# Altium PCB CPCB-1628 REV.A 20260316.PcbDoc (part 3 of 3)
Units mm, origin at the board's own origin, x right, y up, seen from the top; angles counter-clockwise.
Board outline 103 x 58.8 mm, 4 copper layers (Top Layer 1, Layer1, Layer2, Bottom Layer 1), stack 0.603 mm thick; 176 components, 137 nets, 518 pads, 340 vias.
Unrouted connection lines stored in the file: 10.
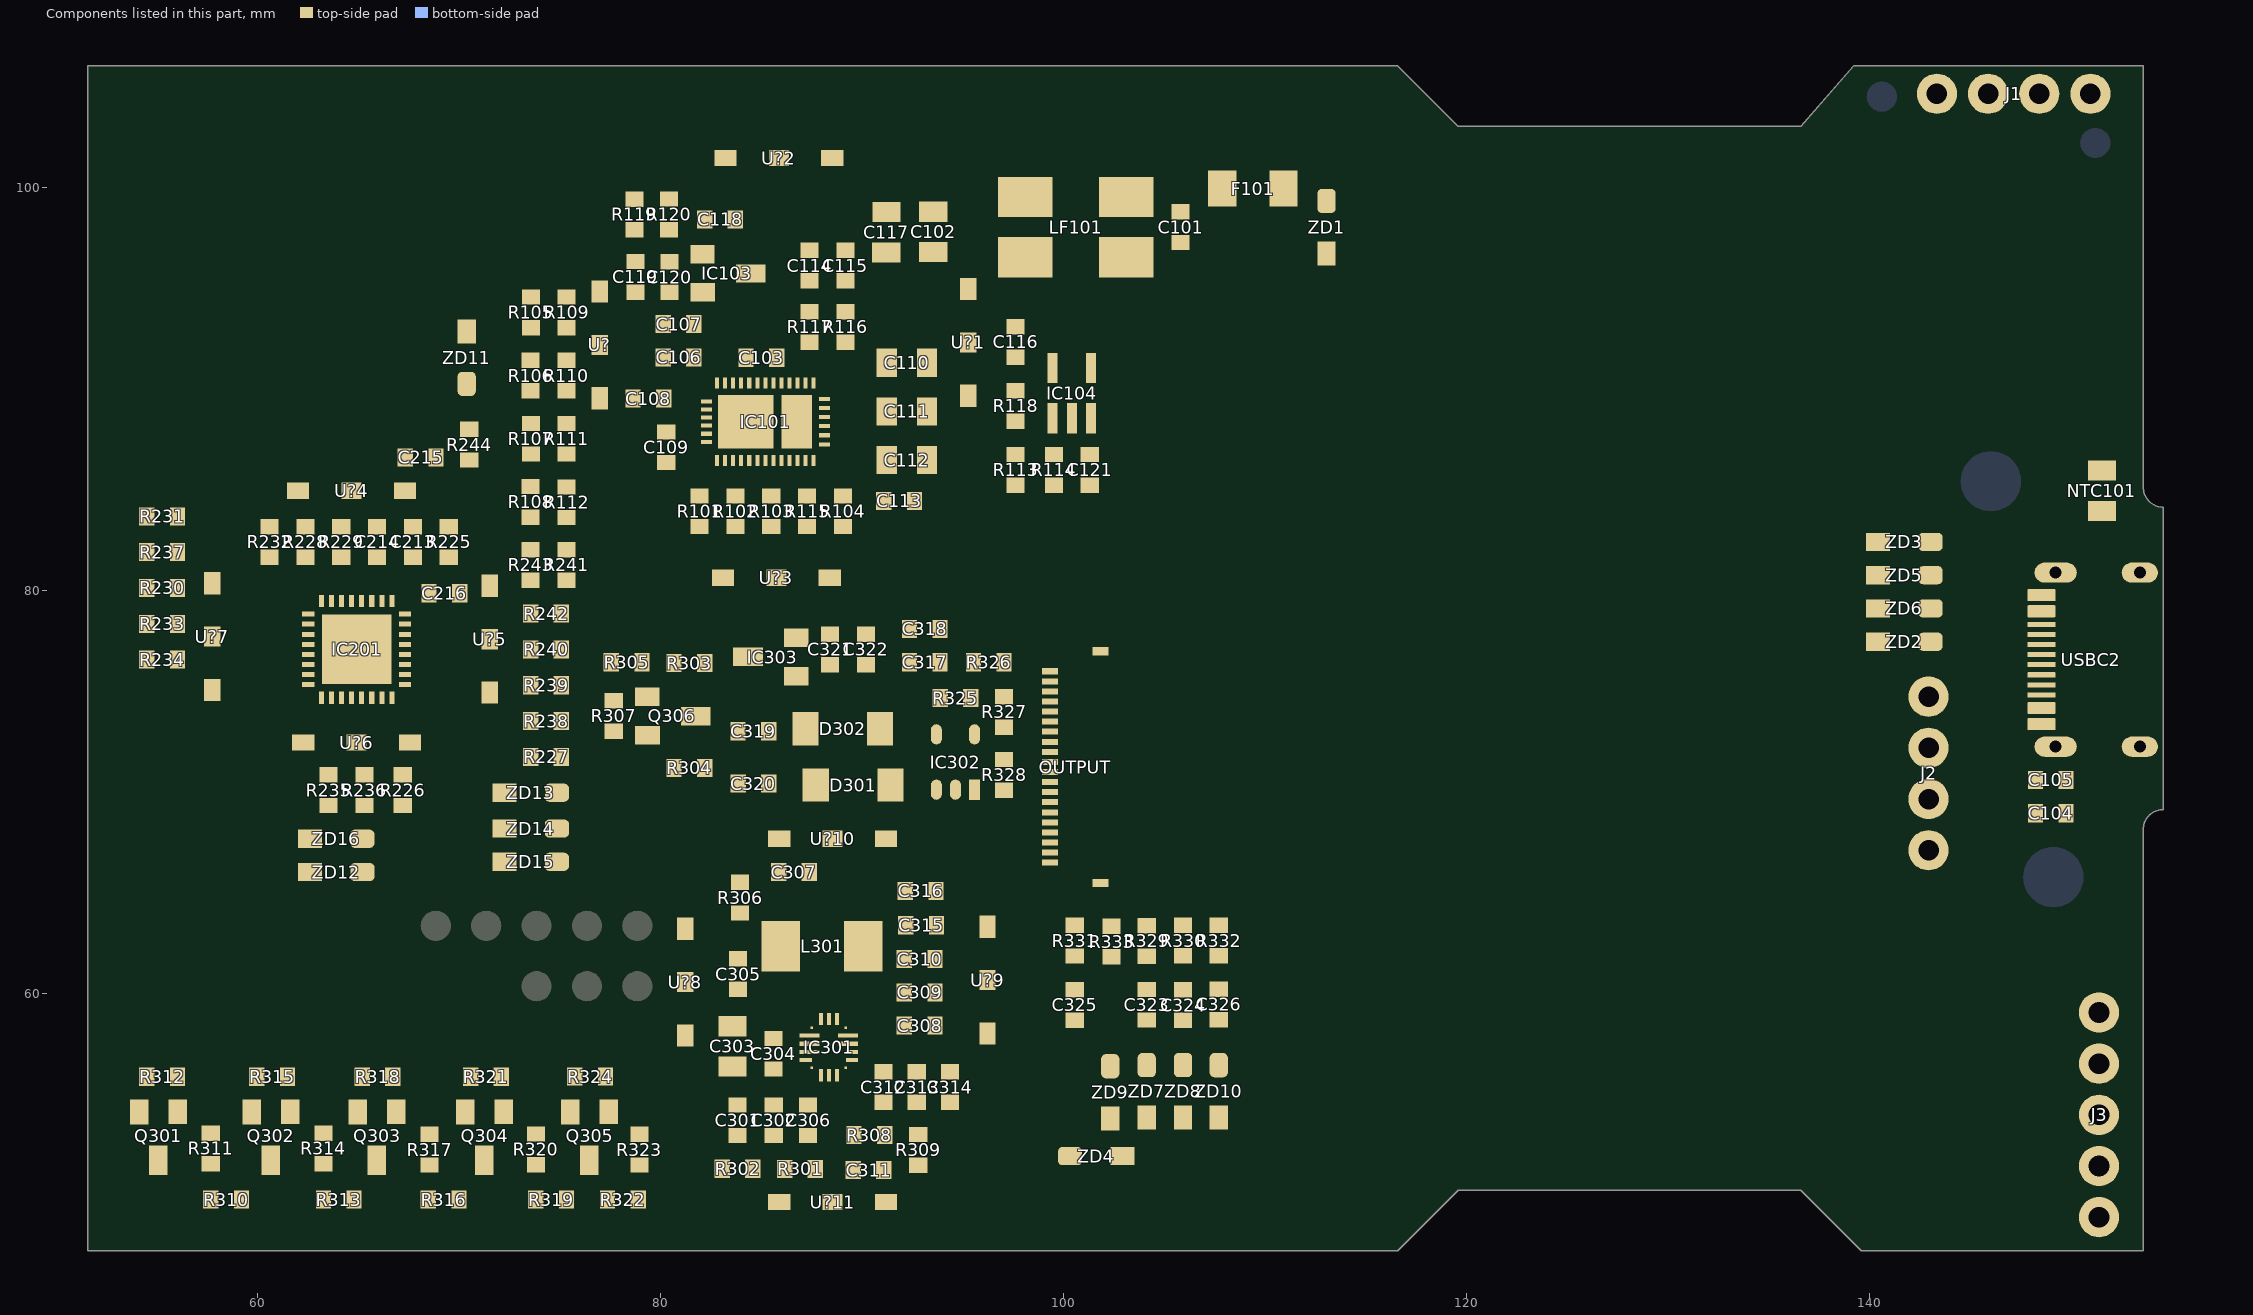
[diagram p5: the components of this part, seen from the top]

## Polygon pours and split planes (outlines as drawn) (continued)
NetC305_1 on Top Layer 1 "NONET_L-01_P-001" (hatched Horizontal grid 0.1 track 0.11, pour order 207): 84.398,60.131 84.287,60.243 84.287,60.612 83.322,60.612 83.322,59.835 83.34,59.818 84.307,59.818 84.403,59.913
NetC305_2 on Top Layer 1 "NONET_L-01_P-001" (hatched Horizontal grid 0.1 track 0.11, pour order 208): 82.388,64.568 82.388,61.058 84.647,61.058 85.429,60.276 85.429,58.835 85.59,58.674 86.469,58.674 86.469,59.876 86.918,60.325 87.739,60.325 87.866,60.452 87.866,64.643 87.739,64.77 82.59,64.77
NetC307_2 on Top Layer 1 "NONET_L-01_P-001" (hatched Horizontal grid 0.1 track 0.11, pour order 209): 86.215,65.495 86.215,66.548 83.802,66.548 83.421,66.167 83.421,65.151 84.437,65.151 84.766,65.48
ADCIN2 on Top Layer 1 "NONET_L-01_P-001" (hatched Horizontal grid 0.1 track 0.11, pour order 116): 74.841,90.343 74.851,90.352 75.803,90.352 75.803,89.206 76.552,88.457 76.552,88.206 76.265,87.92 74.83,87.92
TP1 on Top Layer 1 "NONET_L-01_P-001" (hatched Horizontal grid 0.1 track 0.11, pour order 314): 69.208,88.812 69.82,89.424 69.82,90.94 70.776,90.94 70.954,90.762 70.954,87.473 69.215,87.473
TS on Top Layer 1 "NONET_L-01_P-001" (hatched Horizontal grid 0.1 track 0.11, pour order 49): 33 vertices, not listed, extent 58.752,48.013 93.22,51.882
SGND on Top Layer 1 "NONET_L-01_P-001" (hatched Horizontal grid 0.1 track 0.11, pour order 445): 138.938,88.392 138.557,88.773 138.938,88.773
NetIC101_13 on Top Layer 1 "NONET_L-01_P-001" (hatched Horizontal grid 0.1 track 0.11, pour order 65): 87.819,85.089 86.789,85.089 86.789,84.334 87.819,84.334
PPHV on Top Layer 1 "NONET_L-01_P-001" (hatched Horizontal grid 0.1 track 0.11, pour order 4): 18 vertices, not listed, extent 87.893,83.985 91.694,92.075
NetIC101_18 on Top Layer 1 "NONET_L-01_P-001" (hatched Horizontal grid 0.1 track 0.11, pour order 67): 89.482,85.217 88.562,85.217 88.562,84.32 89.482,84.32
NetQ305_1 on Top Layer 1 "NONET_L-01_P-001" (hatched Horizontal grid 0.1 track 0.11, pour order 35): 75.871,52.752 77.829,52.752 78.5,53.424 79.516,53.424 79.516,52.584 78.584,52.584 76.902,50.901 75.852,50.901
NetIC201_31 on Top Layer 1 "NONET_L-01_P-001" (hatched Horizontal grid 0.1 track 0.11, pour order 177): 73.921,79.342 73.889,79.375 73.152,79.375 73.152,78.84 73.01,78.698 73.01,78.523 73.225,78.307 73.921,78.307
NetIC201_6 on Top Layer 1 "NONET_L-01_P-001" (hatched Horizontal grid 0.1 track 0.11, pour order 95): 62.896,81.258 62.896,82.042 61.793,82.042 61.793,81.362 61.907,81.248
NetIC201_8 on Top Layer 1 "NONET_L-01_P-001" (hatched Horizontal grid 0.1 track 0.11, pour order 131): 55.598,78.847 56.426,78.847 56.534,78.739 56.534,78.666 56.393,78.525 56.393,77.859 55.601,77.859
+VBUS on Top Layer 1 "NONET_L-01_P-001" (hatched Horizontal grid 0.1 track 0.11, pour order 328): 99.541,100.754 99.541,105.461 82.22,105.461 81.444,104.685 81.444,100.754 82.332,100.754 82.22,100.865 82.22,102.217 82.817,102.814 89.267,102.814 89.456,102.624 89.456,101.011 89.157,100.711 99.531,100.711 99.535,100.707
INT_TPS25751D on Top Layer 1 "NONET_L-01_P-001" (hatched Horizontal grid 0.1 track 0.11, pour order 47): 54.864,84.328 53.004,84.328 52.558,83.882 52.558,76.69 53.16,76.088 54.873,76.088 54.873,77.112 53.284,77.112 52.862,77.534 52.862,82.961 53.102,83.201 54.864,83.201
SGND on Top Layer 1 "NONET_L-01_P-001" (hatched Horizontal grid 0.1 track 0.11, remove dead copper, pour order 412): 122.214,88.733 115.439,95.508 139.935,95.508 141.375,94.068 141.375,88.733
LED_WHITE on Top Layer 1 "NONET_L-01_P-001" (hatched Horizontal grid 0.1 track 0.11, pour order 353): 150.323,60.121 150.323,57.996 152.439,57.996 152.439,60.121
+3.2V on Top Layer 1 "NONET_L-01_P-001" (hatched Horizontal grid 0.1 track 0.11, pour order 352): 151.74,105.589 152.019,105.31 152.019,103.621 147.421,103.621 147.421,105.619
GND on Top Layer 1 "NONET_L-01_P-001" (hatched Horizontal grid 0.1 track 0.11, pour order 349): 146.39,105.642 146.844,105.187 146.844,103.688 142.174,103.688 142.174,105.671
+3.3V on Top Layer 1 "NONET_L-01_P-001" (hatched Horizontal grid 0.1 track 0.11, pour order 180): 17 vertices, not listed, extent 78.201,90.101 82.842,95.322
LDO-3V3 on Top Layer 1 "NONET_L-01_P-001" (hatched Horizontal grid 0.1 track 0.11, pour order 343): 80.561,89.996 80.299,89.996 79.523,90.771 79.256,90.771 79.087,90.602 79.087,90.331 79.742,89.676 79.742,89.085 80.549,89.085 80.56,89.074 80.56,89.588 80.729,89.757 80.729,89.828
NetIC101_36 on Top Layer 1 "NONET_L-01_P-001" (hatched Horizontal grid 0.1 track 0.11, pour order 342): 80.867,99.041 80.867,100.272 80.478,100.661 80.057,100.661 79.91,100.514 79.91,99.036
NetIC101_37 on Top Layer 1 "NONET_L-01_P-001" (hatched Horizontal grid 0.1 track 0.11, pour order 341): 79.151,99.023 79.151,100.554 79.121,100.584 78.359,100.584 78.218,100.443 78.218,99.023
+VBUS on Top Layer 1 "NONET_L-01_P-001" (hatched Horizontal grid 0.1 track 0.11, pour order 324): 25 vertices, not listed, extent 81.444,90.086 99.541,100.754
GND on Top Layer 1 "NONET_L-01_P-001" (hatched Horizontal grid 0.1 track 0.11, pour order 313): 152.827,85.468 152.827,87.503 151.13,87.503 150.79,87.163 150.79,85.478
NetIC102_4 on Top Layer 1 "NONET_L-01_P-001" (hatched Horizontal grid 0.1 track 0.11, pour order 312): 150.771,84.533 150.771,83.036 151.13,82.677 152.019,82.677 152.273,82.931 152.273,84.533
INT_BATT_IC on Top Layer 1 "NONET_L-01_P-001" (hatched Horizontal grid 0.1 track 0.11, pour order 45): 54.044,80.773 54.909,80.773 54.909,77.723 54.026,77.723
INT_BQ25622 on Top Layer 1 "NONET_L-01_P-001" (hatched Horizontal grid 0.1 track 0.11, pour order 46): 53.233,82.402 54.9,82.402 54.904,82.406 54.904,81.398 54.898,81.392 53.233,81.392
NetF101_1 on Top Layer 1 "NONET_L-01_P-001" (hatched Horizontal grid 0.1 track 0.11, pour order 183): 121.563,100.143 116.275,105.432 110.258,105.432 110.067,105.241 110.067,98.298 117.983,98.298 121.563,98.298
CC1 on Top Layer 1 "NONET_L-01_P-001" (hatched Horizontal grid 0.1 track 0.11, pour order 197): 143.663,76.941 143.663,77.929 143.626,77.967 141.848,77.967 141.65,77.769 141.65,77.265 141.974,76.941
D- on Top Layer 1 "NONET_L-01_P-001" (hatched Horizontal grid 0.1 track 0.11, pour order 196): 143.675,78.613 143.675,79.601 143.638,79.639 141.86,79.639 141.663,79.441 141.663,78.937 141.986,78.613
D+ on Top Layer 1 "NONET_L-01_P-001" (hatched Horizontal grid 0.1 track 0.11, pour order 195): 143.68,80.257 143.68,81.245 143.642,81.283 141.864,81.283 141.667,81.085 141.667,80.58 141.991,80.257
CC2 on Top Layer 1 "NONET_L-01_P-001" (hatched Horizontal grid 0.1 track 0.11, pour order 194): 143.674,81.905 143.674,82.894 143.637,82.931 141.859,82.931 141.662,82.734 141.662,82.229 141.985,81.905
NetC104_1 on Top Layer 1 "NONET_L-01_P-001" (hatched Horizontal grid 0.1 track 0.11, pour order 193): 19 vertices, not listed, extent 148.159,68.453 154.235,81.534
no net on Top Layer 1 "NONET_L-01_P-001" (hatched Horizontal grid 0.1 track 0.11, pour order 191): 149.16,79.217 149.16,78.744 149.166,78.739
VBUS on Top Layer 1 "NONET_L-01_P-001" (hatched Horizontal grid 0.1 track 0.11, pour order 185): 108.615,99.017 108.047,98.449 101.665,98.449 101.665,105.094 101.981,105.41 108.615,105.41
LDO-1V5 on Top Layer 1 "NONET_L-01_P-001" (hatched Horizontal grid 0.1 track 0.11, pour order 17): 80.899,88.138 80.736,87.975 80.736,87.513 79.811,87.513 79.802,87.504 79.802,88.239 79.819,88.255 80.743,88.255
PPHV on Top Layer 1 "NONET_L-01_P-001" (hatched Horizontal grid 0.1 track 0.11, pour order 147): 87.889,88.215 87.889,87.221 89.901,87.221 89.923,87.244 89.255,87.912 89.255,88.215
NetIC201_24 on Top Layer 1 "NONET_L-01_P-001" (hatched Horizontal grid 0.1 track 0.11, pour order 134): 73.942,71.275 73.134,71.275 73.115,71.295 73.115,71.588 73.017,71.686 73.017,71.788 73.109,71.88 73.109,72.234 73.12,72.245 73.941,72.245 73.944,72.242
NetIC201_26 on Top Layer 1 "NONET_L-01_P-001" (hatched Horizontal grid 0.1 track 0.11, pour order 133): 73.952,73.068 73.144,73.068 73.124,73.088 73.124,73.381 73.026,73.479 73.026,73.581 73.119,73.673 73.119,74.027 73.13,74.038 73.951,74.038 73.954,74.035
NetIC201_9 on Top Layer 1 "NONET_L-01_P-001" (hatched Horizontal grid 0.1 track 0.11, pour order 132): 55.589,77.135 56.417,77.135 56.417,76.762 56.515,76.664 56.515,76.563 56.422,76.47 56.422,76.116 56.411,76.105 55.59,76.105 55.588,76.108
"BSL UART_RX" on Top Layer 1 "NONET_L-01_P-001" (hatched Horizontal grid 0.1 track 0.11, pour order 130): 74.669,74.036 75.458,74.036 75.458,73.076 74.672,73.076
"BSL UART_TX" on Top Layer 1 "NONET_L-01_P-001" (hatched Horizontal grid 0.1 track 0.11, pour order 129): 74.676,75.791 75.465,75.791 75.465,74.831 74.68,74.831
NetIC201_27 on Top Layer 1 "NONET_L-01_P-001" (hatched Horizontal grid 0.1 track 0.11, pour order 126): 73.133,75.777 73.921,75.777 73.921,74.746 73.136,74.746
NetIC201_28 on Top Layer 1 "NONET_L-01_P-001" (hatched Horizontal grid 0.1 track 0.11, pour order 125): 73.128,77.598 73.916,77.598 73.916,76.638 73.131,76.638
NetIC101_28 on Top Layer 1 "NONET_L-01_P-001" (hatched Horizontal grid 0.1 track 0.11, pour order 105): 88.578,91.933 88.65,92.005 88.65,92.71 89.592,92.71 89.604,92.722 89.614,92.712 89.614,91.86 88.578,91.86
NetIC101_29 on Top Layer 1 "NONET_L-01_P-001" (hatched Horizontal grid 0.1 track 0.11, pour order 104): 86.726,92.093 86.908,92.275 86.908,92.726 87.851,92.726 87.863,92.738 87.873,92.729 87.873,91.955 86.726,91.955
NetIC201_7 on Top Layer 1 "NONET_L-01_P-001" (hatched Horizontal grid 0.1 track 0.11, pour order 96): 61.077,81.271 61.076,81.273 61.076,82.055 60.06,82.055 60.06,81.319 60.118,81.261
GND on Top Layer 1 "NONET_L-01_P-001" (hatched Horizontal grid 0.1 track 0.11, pour order 92): 63.436,82.791 63.436,83.503 63.373,83.566 61.849,83.566 61.849,82.873 61.931,82.791
+VBUS on Top Layer 1 "NONET_L-01_P-001" (hatched Horizontal grid 0.1 track 0.11, pour order 87): 87.893,89.601 88.519,90.227 88.519,90.551 88.773,90.805 89.027,90.805 89.281,90.551 89.281,89.001 88.843,88.562 87.893,88.562
"BSL UART_TX" on Top Layer 1 "PG" (hatched Horizontal grid 0.1 track 0.11, pour order 84): 74.176,67.08 76.414,67.08 76.555,66.939 76.555,66.244 76.355,66.044 74.178,66.044
"BSL UART_RX" on Top Layer 1 "NONET_L-01_P-001" (hatched Horizontal grid 0.1 track 0.11, pour order 83): 75.898,69.125 76.01,69.125 76.216,68.919 76.216,68.33 75.57,67.685 74.298,67.685 74.141,67.842 74.141,68.707 75.48,68.707
I2Ct-SCL on Top Layer 1 "NONET_L-01_P-001" (hatched Horizontal grid 0.1 track 0.11, pour order 66): 83.62,85.878 83.248,85.506 83.248,84.445 84.135,84.445 84.135,85.363
INT_TPS25751D on Top Layer 1 "NONET_L-01_P-001" (hatched Horizontal grid 0.1 track 0.11, pour order 64): 85.983,85.095 84.965,85.095 84.965,84.34 85.983,84.34
I2Ct-SDA on Top Layer 1 "NONET_L-01_P-001" (hatched Horizontal grid 0.1 track 0.11, pour order 63): 82.392,85.226 80.254,85.226 80.254,84.44 82.392,84.44
NetIC201_23 on Top Layer 1 "NONET_L-01_P-001" (hatched Horizontal grid 0.1 track 0.11, pour order 62): 67.646,71.241 66.588,71.241 66.588,70.433 67.646,70.433
NetIC201_22 on Top Layer 1 "NONET_L-01_P-001" (hatched Horizontal grid 0.1 track 0.11, pour order 61): 65.865,71.241 64.814,71.241 64.814,70.433 65.865,70.433
NetIC201_21 on Top Layer 1 "NONET_L-01_P-001" (hatched Horizontal grid 0.1 track 0.11, pour order 60): 63.962,71.235 63.041,71.235 63.041,70.336 63.962,70.336
NetR322_1 on Top Layer 1 "NONET_L-01_P-001" (hatched Horizontal grid 0.1 track 0.11, pour order 55): 78.459,51.882 78.459,49.226 79.459,49.226 79.459,51.882
NetR319_1 on Top Layer 1 "NONET_L-01_P-001" (hatched Horizontal grid 0.1 track 0.11, pour order 53): 73.359,51.905 73.359,49.249 74.301,49.249 74.301,51.905
NetR316_1 on Top Layer 1 "NONET_L-01_P-001" (hatched Horizontal grid 0.1 track 0.11, pour order 52): 68.053,51.926 68.053,49.27 68.995,49.27 68.995,51.926
NetR313_1 on Top Layer 1 "NONET_L-01_P-001" (hatched Horizontal grid 0.1 track 0.11, pour order 51): 62.778,51.979 62.778,49.323 63.72,49.323 63.72,51.979
NetR310_1 on Top Layer 1 "NONET_L-01_P-001" (hatched Horizontal grid 0.1 track 0.11, pour order 50): 57.215,51.975 57.215,49.319 58.157,49.319 58.157,51.975
INT_BQ25622 on Top Layer 1 "NONET_L-01_P-001" (hatched Horizontal grid 0.1 track 0.11, pour order 42): 64.002,69.763 62.301,69.763 62.22,69.682 62.22,69.098 62.363,68.955 64.002,68.955
SWCLK on Top Layer 1 "NONET_L-01_P-001" (hatched Horizontal grid 0.1 track 0.11, pour order 39): 74.652,72.258 74.652,71.098 74.159,70.605 74.159,69.694 74.358,69.494 75.344,69.494 75.481,69.631 75.481,72.258
PG on Top Layer 1 "NONET_L-01_P-001" (hatched Horizontal grid 0.1 track 0.11, pour order 38): 73.041,80.936 73.041,80.125 73.661,80.125 74.656,79.129 74.656,78.402 76.272,78.402 76.272,79.314 74.851,79.314 73.996,80.169 73.996,80.926
NetQ304_1 on Top Layer 1 "NONET_L-01_P-001" (hatched Horizontal grid 0.1 track 0.11, pour order 34): 70.673,52.718 72.619,52.718 73.303,53.403 74.319,53.403 74.319,52.556 73.38,52.556 71.704,50.88 70.654,50.88
NetQ303_1 on Top Layer 1 "NONET_L-01_P-001" (hatched Horizontal grid 0.1 track 0.11, pour order 33): 65.396,52.734 67.357,52.734 68.025,53.403 69.041,53.403 69.041,52.641 68.187,52.641 66.427,50.88 65.377,50.88
NetQ302_1 on Top Layer 1 "NONET_L-01_P-001" (hatched Horizontal grid 0.1 track 0.11, pour order 32): 60.142,52.84 62.131,52.84 62.771,53.48 63.787,53.48 63.787,52.675 62.89,52.675 61.173,50.958 60.123,50.958
NetQ301_1 on Top Layer 1 "NONET_L-01_P-001" (hatched Horizontal grid 0.1 track 0.11, pour order 31): 54.52,52.786 56.469,52.786 57.15,53.467 58.166,53.467 58.166,52.653 57.26,52.653 55.551,50.945 54.501,50.945
COLD_HOT on Top Layer 1 "NONET_L-01_P-001" (hatched Horizontal grid 0.1 track 0.11, pour order 30): 76.851,56.333 76.851,53.424 77.914,53.424 77.914,56.237 77.824,56.327
WARM on Top Layer 1 "NONET_L-01_P-001" (hatched Horizontal grid 0.1 track 0.11, pour order 29): 71.682,56.322 71.682,53.403 72.744,53.403 72.744,56.227 72.655,56.316
PRE_WARM on Top Layer 1 "NONET_L-01_P-001" (hatched Horizontal grid 0.1 track 0.11, pour order 28): 66.318,56.333 66.318,53.434 67.381,53.434 67.381,56.238 67.291,56.328
NORMAL on Top Layer 1 "NONET_L-01_P-001" (hatched Horizontal grid 0.1 track 0.11, pour order 27): 61.04,56.323 61.04,53.49 61.046,53.484 62.103,53.484 62.103,56.228 62.013,56.317
PRE_COOL on Top Layer 1 "NONET_L-01_P-001" (hatched Horizontal grid 0.1 track 0.11, pour order 26): 55.501,53.502 55.501,56.386 55.499,56.388 56.388,56.388 56.53,56.246 56.53,53.496
SWDIO on Top Layer 1 "NONET_L-01_P-001" (hatched Horizontal grid 0.1 track 0.11, pour order 25): 64.52,66.56 66.56,66.56 66.727,66.727 66.727,69.755 67.682,69.755 67.704,69.733 67.704,66.305 66.943,65.544 64.514,65.544
BSL_Invoke on Top Layer 1 "NONET_L-01_P-001" (hatched Horizontal grid 0.1 track 0.11, pour order 24): 64.725,69.727 64.725,68.241 64.544,68.06 64.544,67.242 64.643,67.143 65.83,67.143 65.868,67.181 65.868,69.727
+1.8V on Top Layer 1 "NONET_L-01_P-001" (hatched Horizontal grid 0.1 track 0.11, pour order 23): 55.539,84.328 55.539,79.555 56.388,79.555 56.388,80.772 57.277,81.661 57.277,84.328
STAT on Top Layer 1 "NONET_L-01_P-001" (hatched Horizontal grid 0.1 track 0.11, pour order 22): 64.618,82.803 64.618,83.972 64.386,84.204 59.947,84.204 59.346,83.603 59.346,82.787 61.009,82.787 61.009,83.679 61.197,83.866 63.422,83.866 63.713,83.576 63.713,82.803
NRST on Top Layer 1 "NONET_L-01_P-001" (hatched Horizontal grid 0.1 track 0.11, pour order 21): 68.99,82.79 68.99,85.442 68.453,85.979 68.453,87.078 70.993,87.078 70.993,85.471 69.946,84.424 69.946,82.793
+1.8V on Top Layer 1 "NONET_L-01_P-001" (hatched Horizontal grid 0.1 track 0.11, pour order 20): 65.07,80.877 64.666,81.28 65.499,81.28
CC1 on Top Layer 1 "NONET_L-01_P-001" (hatched Horizontal grid 0.1 track 0.11, pour order 7): 88.62,95.8 89.647,95.8 89.647,93.456 89.628,93.436 88.604,93.436
CC2 on Top Layer 1 "NONET_L-01_P-001" (hatched Horizontal grid 0.1 track 0.11, pour order 6): 86.883,95.79 87.911,95.79 87.911,93.473 87.865,93.426 86.868,93.426
GND on Layer2 "NONET_L-01_P-001" (hatched Horizontal grid 0.1 track 0.11, remove dead copper, pour order 546): 22 vertices, not listed, extent 52.077,47.855 152.896,105.527
BAT+ on Layer2 "NONET_L-01_P-001" (hatched Horizontal grid 0.1 track 0.11, pour order 543): 91.563,57.538 101.057,57.538 101.057,54.956 100.965,54.864 91.563,54.864
LED_GREEN3 on Layer2 "NONET_L-01_P-001" (hatched Horizontal grid 0.1 track 0.11, pour order 513): 141.845,68.17 141.845,66.045 143.96,66.045 143.96,68.17
LED_GREEN2 on Layer2 "NONET_L-01_P-001" (hatched Horizontal grid 0.1 track 0.11, pour order 512): 141.857,70.703 141.857,68.579 143.972,68.579 143.972,70.703
LED_GREEN1 on Layer2 "NONET_L-01_P-001" (hatched Horizontal grid 0.1 track 0.11, pour order 511): 141.857,73.237 141.857,71.112 143.972,71.112 143.972,73.237
LED_GREEN4 on Layer2 "NONET_L-01_P-001" (hatched Horizontal grid 0.1 track 0.11, pour order 510): 141.797,75.795 141.797,73.67 143.912,73.67 143.912,75.795
LED_RED1 on Layer2 "NONET_L-01_P-001" (hatched Horizontal grid 0.1 track 0.11, pour order 509): 150.333,50.021 150.333,47.896 152.449,47.896 152.449,50.021
LED_RED2 on Layer2 "NONET_L-01_P-001" (hatched Horizontal grid 0.1 track 0.11, pour order 508): 150.323,52.49 150.323,50.365 152.439,50.365 152.439,52.49
LED_RED3 on Layer2 "NONET_L-01_P-001" (hatched Horizontal grid 0.1 track 0.11, pour order 507): 150.314,55.066 150.314,52.941 152.429,52.941 152.429,55.066
LED_RED4 on Layer2 "NONET_L-01_P-001" (hatched Horizontal grid 0.1 track 0.11, pour order 506): 150.304,57.632 150.304,55.507 152.419,55.507 152.419,57.632
LED_WHITE on Layer2 "NONET_L-01_P-001" (hatched Horizontal grid 0.1 track 0.11, pour order 505): 150.323,60.14 150.323,58.015 152.439,58.015 152.439,60.14
GND on Layer2 "NONET_L-01_P-001" (hatched Horizontal grid 0.1 track 0.11, pour order 203): 125.795,102.318 137.078,102.271 140.482,105.674 146.382,105.674 146.861,105.196 146.861,104.189 141.414,98.742 125.795,98.742
+3.2V on Layer2 "NONET_L-01_P-001" (hatched Horizontal grid 0.1 track 0.11, pour order 478): 95.304,79.932 95.304,77.416 95.407,77.313 95.893,77.313 99.181,80.6 116.418,80.6 119.302,83.484 119.302,88.379 118.161,89.519 117.306,89.519 117.306,84.853 115.204,82.75 98.122,82.75
+VBUS on Layer2 "NONET_L-01_P-001" (hatched Horizontal grid 0.1 track 0.11, pour order 477): 88.011,75.117 88.011,74.262 88.075,74.198 89.572,74.198 92.635,77.261 92.635,96.369 94.742,98.475 91.782,98.475 91.781,77.66 89.239,75.117
PPHV on Layer2 "NONET_L-01_P-001" (hatched Horizontal grid 0.1 track 0.11, pour order 475): 82.641,66.03 82.641,73.727 89.127,80.214 89.127,88.332 90.578,88.332 90.578,79.083 84.074,72.579 84.074,66.03
PPHV on Layer2 "NONET_L-01_P-001" (hatched Horizontal grid 0.1 track 0.11, pour order 473): 84.074,66.03 82.617,66.03 82.617,55.178 83.621,54.174 84.95,54.174 85.287,54.511 85.287,55.957 84.113,57.131
NetC305_2 on Layer2 "NONET_L-01_P-001" (hatched Horizontal grid 0.1 track 0.11, pour order 211): 88.798,58.873 88.798,56.388 86.672,56.388 85.21,57.85 85.21,60.353 85.21,64.77 87.694,64.77 87.874,64.59 87.874,60.423 87.777,60.325 86.901,60.325 86.486,59.91 86.486,59.405 87.014,58.877
GND on Layer2 "NONET_L-01_P-001" (hatched Horizontal grid 0.1 track 0.11, pour order 435): 126.345,99.134 116.867,89.655 114.5,92.022 124.796,102.318 126.345,102.318
+3.2V on Layer2 "NONET_L-01_P-001" (hatched Horizontal grid 0.1 track 0.11, pour order 416): 117.306,88.379 117.306,89.519 125.746,97.958 141.671,97.958 147.368,103.656 147.368,105.635 152.019,105.635 152.019,104.17 142.957,95.109 126.032,95.109 119.302,88.379
+3.2V on Layer2 "NONET_L-01_P-001" (hatched Horizontal grid 0.1 track 0.11, pour order 351): 150.403,105.599 150.86,105.142 150.86,103.786 147.421,103.786 147.421,105.619
GND on Layer2 "NONET_L-01_P-001" (hatched Horizontal grid 0.1 track 0.11, pour order 350): 146.461,105.571 146.844,105.187 146.844,103.792 143.424,103.792 143.424,105.592
+VBUS on Layer2 "NONET_L-01_P-001" (hatched Horizontal grid 0.1 track 0.11, pour order 332): 99.545,105.455 97.658,105.463 89.782,105.459 83.263,98.94 83.263,91.511 83.252,91.5 83.371,91.381 86.249,91.381 86.249,97.425 86.868,98.044 96.074,98.044 96.493,98.463 99.563,98.463
+VBUS on Layer2 "NONET_L-01_P-001" (hatched Horizontal grid 0.1 track 0.11, pour order 97): 88.636,90.551 89.191,90.551 89.191,88.86 85.892,88.86 83.252,91.5 83.252,94.107 85.419,94.107 85.419,92.212 87.08,90.551
GND on Layer1 "NONET_L-01_P-001" (hatched Horizontal grid 0.1 track 0.11, remove dead copper, pour order 545): 22 vertices, not listed, extent 52.077,47.855 152.896,105.527
BAT+ on Layer1 "NONET_L-01_P-001" (hatched Horizontal grid 0.1 track 0.11, pour order 544): 90.678,57.533 101.057,57.538 101.057,54.956 100.965,54.864 91.186,54.864 90.678,55.372
LED_GREEN4 on Layer1 "NONET_L-01_P-001" (hatched Horizontal grid 0.1 track 0.11, pour order 501): 141.78,75.789 141.78,73.664 143.896,73.664 143.896,75.789
LED_RED1 on Layer1 "NONET_L-01_P-001" (hatched Horizontal grid 0.1 track 0.11, pour order 500): 150.336,50.004 150.336,47.879 152.452,47.879 152.452,50.004
LED_RED2 on Layer1 "NONET_L-01_P-001" (hatched Horizontal grid 0.1 track 0.11, pour order 499): 150.336,52.485 150.336,50.36 152.452,50.36 152.452,52.485
LED_RED3 on Layer1 "NONET_L-01_P-001" (hatched Horizontal grid 0.1 track 0.11, pour order 498): 150.321,55.067 150.321,52.942 152.436,52.942 152.436,55.067
LED_RED4 on Layer1 "NONET_L-01_P-001" (hatched Horizontal grid 0.1 track 0.11, pour order 497): 150.308,57.601 150.308,55.476 152.424,55.476 152.424,57.601
LED_WHITE on Layer1 "NONET_L-01_P-001" (hatched Horizontal grid 0.1 track 0.11, pour order 496): 150.326,60.136 150.326,58.011 152.442,58.011 152.442,60.136
+3.3V on Layer1 "NONET_L-01_P-001" (hatched Horizontal grid 0.1 track 0.11, pour order 100): 81.862,90.821 81.862,77.089 82.553,77.089 82.553,90.675 82.407,90.821
+3.3V on Layer1 "NONET_L-01_P-001" (hatched Horizontal grid 0.1 track 0.11, pour order 459): 81.822,76.992 81.25,76.992 81.026,77.216 81.026,77.903 81.82,78.697
SGND on Layer1 "NONET_L-01_P-001" (hatched Horizontal grid 0.1 track 0.11, pour order 329): 139.832,81.649 141.549,83.366 142.902,83.366 142.902,95.147 139.832,95.147
SGND on Layer1 "NONET_L-01_P-001" (hatched Horizontal grid 0.1 track 0.11, pour order 439): 21 vertices, not listed, extent 138.84,63.5 152.984,90.534
SGND on Layer1 "NONET_L-01_P-001" (hatched Horizontal grid 0.1 track 0.11, pour order 438): 146.939,81.788 146.939,80.391 147.893,79.437 147.893,74.233 147.32,73.66 147.32,69.723 149.249,67.794 152.984,67.794 152.984,81.331 152.527,81.788
+1.8V on Layer1 "NONET_L-01_P-001" (hatched Horizontal grid 0.1 track 0.11, pour order 405): 64.921,81.212 64.447,81.686 56.662,81.686 56.37,81.978 56.37,83.43 57.304,83.43 57.304,82.835 57.742,82.397 68.581,82.397 68.837,82.141 68.837,81.234
+3.2V on Layer1 "NONET_L-01_P-001" (hatched Horizontal grid 0.1 track 0.11, pour order 310): 151.781,105.589 152.019,105.351 152.019,103.643 147.421,103.643 147.421,105.619
GND on Layer1 "NONET_L-01_P-001" (hatched Horizontal grid 0.1 track 0.11, pour order 306): 146.4,105.632 146.844,105.187 146.844,103.677 142.185,103.677 142.185,105.661
+VBUS on Layer1 "NONET_L-01_P-001" (hatched Horizontal grid 0.1 track 0.11, pour order 330): 17 vertices, not listed, extent 82.788,91.129 99.548,105.458
+3.3V on Layer1 "NONET_L-01_P-001" (hatched Horizontal grid 0.1 track 0.11, pour order 102): 81.915,90.821 81.302,90.821 81.153,90.672 81.153,90.297 81.915,89.535
GND on Bottom Layer 1 "NONET_L-01_P-001" (hatched Horizontal grid 0.1 track 0.11, remove dead copper, pour order 547): 22 vertices, not listed, extent 52.077,47.855 152.896,105.527
NetF101_1 on Bottom Layer 1 "NONET_L-01_P-001" (hatched Horizontal grid 0.1 track 0.11, pour order 534): 146.556,82.55 146.556,74.813 146.871,74.498 146.871,73.968 146.854,73.951 145.251,73.951 144.907,74.295 144.907,81.983 144.34,82.55
NetF101_1 on Bottom Layer 1 "NONET_L-01_P-001" (hatched Horizontal grid 0.1 track 0.11, pour order 450): 146.556,82.55 147.962,83.956 149.163,83.956 149.163,88.877 146.785,91.255 144.34,91.255 144.34,82.55
SGND on Bottom Layer 1 "NONET_L-01_P-001" (hatched Horizontal grid 0.1 track 0.11, pour order 198): 147.829,73.625 144.803,73.625 144.803,63.5 152.984,63.5 152.984,67.794 149.249,67.794 148.59,68.453 148.59,70.993 148.082,71.501 147.828,71.755 147.828,72.771
LED_GREEN3 on Bottom Layer 1 "NONET_L-01_P-001" (hatched Horizontal grid 0.1 track 0.11, pour order 522): 141.84,68.202 141.84,66.078 143.955,66.078 143.955,68.202
LED_GREEN2 on Bottom Layer 1 "NONET_L-01_P-001" (hatched Horizontal grid 0.1 track 0.11, pour order 521): 141.84,70.706 141.84,68.581 143.955,68.581 143.955,70.706
LED_GREEN1 on Bottom Layer 1 "NONET_L-01_P-001" (hatched Horizontal grid 0.1 track 0.11, pour order 520): 141.84,73.241 141.84,71.116 143.955,71.116 143.955,73.241
LED_GREEN4 on Bottom Layer 1 "NONET_L-01_P-001" (hatched Horizontal grid 0.1 track 0.11, pour order 519): 141.808,75.792 141.808,73.667 143.923,73.667 143.923,75.792
LED_RED1 on Bottom Layer 1 "NONET_L-01_P-001" (hatched Horizontal grid 0.1 track 0.11, pour order 518): 150.324,50.019 150.324,47.894 152.44,47.894 152.44,50.019
LED_RED2 on Bottom Layer 1 "NONET_L-01_P-001" (hatched Horizontal grid 0.1 track 0.11, pour order 517): 150.324,52.513 150.324,50.389 152.44,50.389 152.44,52.513
LED_RED3 on Bottom Layer 1 "NONET_L-01_P-001" (hatched Horizontal grid 0.1 track 0.11, pour order 516): 150.322,55.096 150.322,52.971 152.438,52.971 152.438,55.096
LED_RED4 on Bottom Layer 1 "NONET_L-01_P-001" (hatched Horizontal grid 0.1 track 0.11, pour order 515): 150.269,57.622 150.269,55.498 152.385,55.498 152.385,57.622
LED_WHITE on Bottom Layer 1 "NONET_L-01_P-001" (hatched Horizontal grid 0.1 track 0.11, pour order 514): 150.297,60.11 150.297,57.985 152.413,57.985 152.413,60.11
NetC305_2 on Bottom Layer 1 "NONET_L-01_P-001" (hatched Horizontal grid 0.1 track 0.11, pour order 212): 89.069,58.873 89.091,58.851 89.091,56.388 86.809,56.388 85.501,57.696 85.501,60.19 82.352,63.338 82.352,64.77 87.944,64.77 87.944,60.473 87.796,60.325 86.995,60.325 86.565,59.895 86.565,59.514 87.202,58.877
+3.2V on Bottom Layer 1 "NONET_L-01_P-001" (hatched Horizontal grid 0.1 track 0.11, pour order 453): 152.273,104.648 151.293,105.628 147.351,105.628 147.351,103.779 149.911,101.219 152.273,101.219
GND on Bottom Layer 1 "NONET_L-01_P-001" (hatched Horizontal grid 0.1 track 0.11, pour order 451): 146.836,103.819 146.836,105.217 146.47,105.583 139.446,105.583 139.446,103.427 146.108,103.427 146.497,103.816
SGND on Bottom Layer 1 "NONET_L-01_P-001" (hatched Horizontal grid 0.1 track 0.11, pour order 440): 139.495,63.521 139.095,63.521 138.829,63.787 138.829,88.462 138.505,88.786 138.505,92.169 142.706,92.169 143.525,91.349 143.525,83.413 143.511,83.398 141.599,83.398 141.214,83.014 141.214,76.77 139.495,75.051
SGND on Bottom Layer 1 "NONET_L-01_P-001" (hatched Horizontal grid 0.1 track 0.11, pour order 437): 146.939,81.788 146.939,80.391 147.893,79.437 147.893,74.233 147.32,73.66 147.32,69.723 149.249,67.794 152.984,67.794 152.984,81.331 152.527,81.788
NetC305_2 on Bottom Layer 1 "NONET_L-01_P-001" (hatched Horizontal grid 0.1 track 0.11, pour order 213): 82.37,63.361 82.356,63.347 82.356,61.133 82.504,60.985 84.765,60.985

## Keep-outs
Keep-Out Layer:
  circle w0.013: c65.063,61.643 r2.2
  circle w0.013: c65.063,91.643 r2.2
  circle w0.013: c136.063,91.643 r2.1
  circle w0.127: c149.714,79.472 r0.325
  circle w0.127: c149.713,73.69 r0.325
  lines w0.013: 139.189,106.043 153.563,106.043 ; 139.564,47.243 136.563,50.243 119.563,50.243 116.563,47.243 51.563,47.243 51.563,106.043 116.563,106.043 119.563,103.043 136.563,103.043 ; 140.563,47.243 153.563,47.243 ; 153.563,47.244 153.563,68.143 cw(c154.563,68.143) 154.563,69.143 154.563,84.143 cw(c154.563,85.143) 153.563,85.143 153.563,106.041 ; 136.563,103.043 139.189,106.044 136.563,103.043 ; 119.863,59.743 135.954,59.743 ccw(c137.063,61.643) 138.264,63.487 138.263,88.143 119.863,88.143 119.863,59.743

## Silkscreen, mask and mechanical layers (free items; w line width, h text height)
Top Overlay:
  circle w0.15: c73.827,60.373 r0.8
  circle w0.15: c76.327,60.373 r0.8
  circle w0.15: c78.827,60.373 r0.8
  circle w0.15: c76.327,63.373 r0.8
  circle w0.15: c73.827,63.373 r0.8
  circle w0.15: c71.327,63.373 r0.8
  circle w0.15: c68.827,63.373 r0.8
  circle w0.15: c78.827,63.373 r0.8
  lines w0.1: 76.327,78.867 75.946,79.248 76.992,79.248 81.661,79.248 ; 77.644,95.203 77.644,93.806 78.105,93.345 78.74,93.345 78.994,93.345 78.74,93.599 ; 81.026,56.896 82.169,56.896 81.924,56.651 ; 81.661,81.788 81.28,82.169 89.789,82.169
  text "TP6" at 73.181,61.541 h1
  text "TP3" at 75.467,61.541 h1
  text "TP1" at 68.162,61.53 h1
  text "TP2" at 70.644,61.53 h1
  text "TP7" at 78.078,61.53 h1
  text "TP5" at 73.178,58.366 h1
  text "TP4" at 75.468,58.355 h1
  text "CPCB-1628 REV.A" at 99.996,48.453 h1
Bottom Overlay:
  circle w0.3: c146.001,85.434 r1.656
  circle w0.3: c140.589,104.521 r0.909
  circle w0.3: c151.185,102.227 r0.909
  circle w0.3: c149.098,65.786 r1.656
Mechanical 1:
  circle w0.013: c136.063,91.643 r2.1
  circle w0.013: c65.063,91.643 r2.2
  circle w0.013: c65.063,61.643 r2.2
  lines w0.013: 135.954,59.743 119.863,59.743 119.863,88.143 138.263,88.143 138.263,63.488 ; 135.955,59.743 ccw(c137.063,61.643) 138.264,63.487 ; 139.19,106.043 153.563,106.043 153.563,85.143 ccw(c154.563,85.143) 154.563,84.143 154.563,69.143 ccw(c154.563,68.143) 153.563,68.143 153.563,47.243 139.564,47.243 136.563,50.243 119.563,50.243 116.563,47.243 51.563,47.243 51.563,106.043 116.563,106.043 119.563,103.043 136.563,103.043 ; 136.563,103.043 139.189,106.044 136.563,103.043
Mechanical 7:
  drawing of 156 lines, arcs and shapes, not listed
